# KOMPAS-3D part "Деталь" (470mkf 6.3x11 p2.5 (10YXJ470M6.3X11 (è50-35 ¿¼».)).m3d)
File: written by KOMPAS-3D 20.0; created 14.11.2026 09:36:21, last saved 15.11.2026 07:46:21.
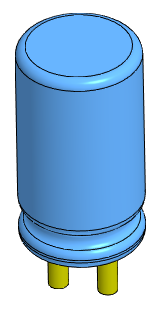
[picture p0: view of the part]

Document properties: Полное имя файла: D:\myProjects\Progect_esp32\box_compas\прочее\470mkf 6.3x11 p2.5 (10YXJ470M6.3X11 (К50-35 имп.)).m3d

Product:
- Part/product: Деталь
    Масса: 0.00265163

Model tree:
1. Эскиз:1
2. Элемент вращения:1
     Угол 1 = 360
3. Скругление:1  (with: Элемент вращения:1)
     Радиус = 0.5
4. Эскиз:2  (with: Элемент вращения:1, Скругление:1)
5. Элемент выдавливания:1
     Расстояние 1 = 3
